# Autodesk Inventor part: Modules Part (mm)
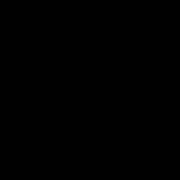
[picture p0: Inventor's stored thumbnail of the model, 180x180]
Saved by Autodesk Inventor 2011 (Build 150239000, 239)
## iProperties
Created: 2008-05
Part Number: Modules Part (mm)
Document SubType Name: Modeling
Designer: Wally
Density: 1 g/cm^3
Author: Wally
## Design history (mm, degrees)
node "Sketch1"
